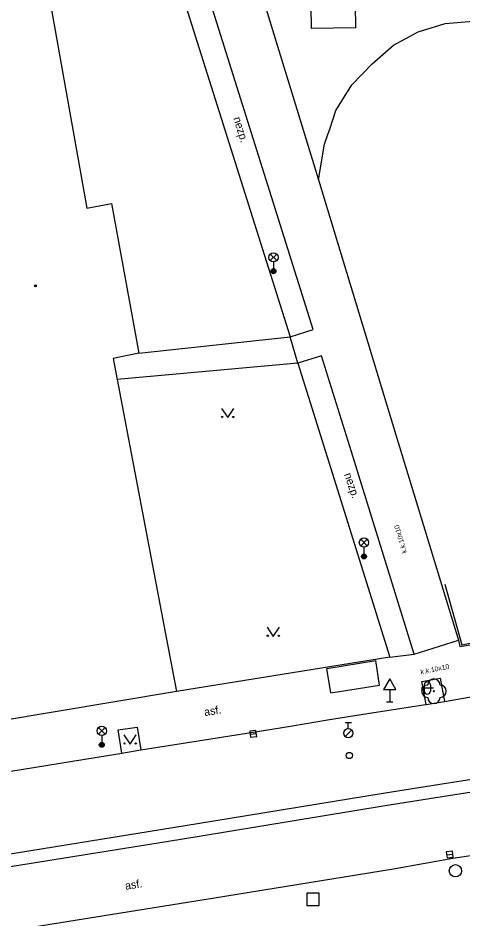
# Model space of a CAD drawing. Extents: x -600309 to -598967, y -1161267 to -1160292.
# Drawn here: x -599181.8 to -599145.7, y -1161124.2 to -1161051.1 of the extents above; entities that cross this region are included whole.
import ezdxf

# ---------------------------------------------------------------- set-up
doc = ezdxf.new("R2010")
doc.units = 0
for name, color, linetype in [('Level 10', 7, 'Continuous'), ('Level 11', 7, 'Continuous'), ('Level 22', 7, 'Continuous'), ('Level 26', 7, 'Continuous'), ('Level 27', 7, 'Continuous'), ('Level 28', 7, 'Continuous'), ('Level 33', 7, 'Continuous'), ('Level 34', 7, 'Continuous'), ('Level 36', 7, 'Continuous'), ('Level 39', 7, 'Continuous'), ('Level 40', 7, 'Continuous'), ('Level 5', 7, 'Continuous'), ('Level 7', 7, 'Continuous'), ('Level 8', 7, 'Continuous'), ('Level 9', 7, 'Continuous')]:
    doc.layers.add(name, color=color, linetype=linetype)

msp = doc.modelspace()

# ---------------------------------------------------------------- linework, layer by layer
at = {"layer": 'Level 10'}
for points in [[(-599147.18, -1161106.56), (-599139.8, -1161105.24)], [(-599171.84, -1161110.48), (-599169.08, -1161110.05), (-599162.7199, -1161109.04), (-599159.53, -1161108.51), (-599156.69, -1161108.03), (-599153.45, -1161107.51), (-599148.74, -1161106.8), (-599148.69, -1161106.79)], [(-599148.69, -1161106.79), (-599147.18, -1161106.56)], [(-599183.6, -1161112.4), (-599173.38, -1161110.75)], [(-599173.38, -1161110.75), (-599171.84, -1161110.48)], [(-599127.19, -1161111.34), (-599131.17, -1161116.8), (-599140.87, -1161118.45), (-599146.51, -1161119.29)], [(-599146.51, -1161119.29), (-599151.34, -1161120.15), (-599165.86, -1161122.5), (-599196.79, -1161127.45), (-599208.59, -1161129.36), (-599217.76, -1161130.81), (-599223.78, -1161126.79)]]:
    msp.add_lwpolyline(points, dxfattribs=at)
at = {"layer": 'Level 11'}
for points in [[(-599159.71, -1161076.94), (-599157.84, -1161076.35), (-599166.53, -1161048.68), (-599167.6599, -1161046.54), (-599175.05, -1161038.42)], [(-599162.5, -1161047.6), (-599157.42, -1161064.19)], [(-599158.03, -1161048.27), (-599154.48, -1161048.1599), (-599154.42, -1161051.87), (-599157.99, -1161051.9099), (-599158.03, -1161048.27)], [(-599157.42, -1161064.19), (-599156.92, -1161061.31), (-599156.67, -1161060.52), (-599156.4699, -1161060), (-599156, -1161058.58), (-599154.7199, -1161056.5), (-599153.06, -1161054.78), (-599151.34, -1161053.28), (-599149.33, -1161052.18), (-599147.14, -1161051.52), (-599144.86, -1161051.33)], [(-599157.42, -1161064.19), (-599151.14, -1161084.9), (-599146.04, -1161101.56)], [(-599172.02, -1161078.26), (-599159.71, -1161076.94)], [(-599149.6599, -1161102.7), (-599154.75, -1161086.28), (-599157.17, -1161078.49), (-599159.09, -1161079.08)], [(-599159.09, -1161079.08), (-599173.76, -1161080.42)], [(-599149.6599, -1161102.7), (-599146.04, -1161101.56)], [(-599146.04, -1161101.56), (-599145.94, -1161102.07), (-599143.03, -1161101.63)], [(-599151.62, -1161102.94), (-599149.6599, -1161102.7)], [(-599156.73, -1161103.87), (-599152.77, -1161103.21)], [(-599152.46, -1161105.22), (-599152.77, -1161103.21)], [(-599156.42, -1161105.84), (-599156.73, -1161103.87)], [(-599148.69, -1161106.79), (-599149.03, -1161104.9099), (-599147.54, -1161104.64), (-599147.18, -1161106.56)], [(-599156.42, -1161105.84), (-599152.46, -1161105.22)], [(-599119.42, -1161109.21), (-599119.94, -1161107.92), (-599131.98, -1161110.59), (-599141.68, -1161112.37), (-599147.5578, -1161113.2881), (-599152.18, -1161114.01), (-599167.25, -1161116.49), (-599181.79, -1161118.82), (-599204.9699, -1161122.5), (-599218.82, -1161124.6599), (-599221.59, -1161124.8), (-599225.08, -1161124.96), (-599236.06, -1161126.61)], [(-599173.38, -1161110.75), (-599173.68, -1161108.86), (-599172.15, -1161108.62), (-599171.84, -1161110.48)], [(-599236.06, -1161126.61), (-599235.9099, -1161127.6), (-599225.55, -1161125.98), (-599221.58, -1161125.8), (-599218.77, -1161125.6599), (-599204.81, -1161123.48), (-599181.6, -1161119.8), (-599169.59, -1161117.88), (-599167.12, -1161117.49), (-599152.01, -1161114.99), (-599147.39, -1161114.27), (-599141.52, -1161113.35), (-599132.1, -1161111.64), (-599125.56, -1161110.17)]]:
    msp.add_lwpolyline(points, dxfattribs=at)
at = {"layer": 'Level 22'}
msp.add_circle((-599148.05, -1161105.71), 0.05, dxfattribs=at)
for centre, start, end in [((-599148.05, -1161105.21), 0, 180), ((-599148.55, -1161105.71), 90, 270), ((-599147.55, -1161105.71), 270, 90), ((-599148.05, -1161106.21), 180, 0)]:
    msp.add_arc(centre, 0.5, start, end, dxfattribs=at)
at = {"layer": 'Level 26'}
msp.add_lwpolyline([(-599158.37, -1161123.1), (-599157.37, -1161123.1), (-599157.37, -1161122.1), (-599158.37, -1161122.1)], close=True, dxfattribs=at)
at = {"layer": 'Level 27'}
for p, q in [((-599162.9679, -1161109.2016), (-599162.4719, -1161109.1384)), ((-599147.008, -1161119.0016), (-599146.512, -1161118.9384))]:
    msp.add_line(p, q, dxfattribs=at)
for points in [[(-599162.9363, -1161109.4496), (-599162.4403, -1161109.3864), (-599162.5035, -1161108.8904), (-599162.9995, -1161108.9536)], [(-599146.9764, -1161119.2496), (-599146.4804, -1161119.1864), (-599146.5436, -1161118.6904), (-599147.0396, -1161118.7536)]]:
    msp.add_lwpolyline(points, close=True, dxfattribs=at)
msp.add_circle((-599146.3, -1161120.29), 0.5, dxfattribs=at)
at = {"layer": 'Level 28'}
for p, q in [((-599155.25, -1161108.245), (-599154.75, -1161108.245)), ((-599155, -1161108.745), (-599155, -1161108.245)), ((-599155.258, -1161109.392), (-599154.728, -1161108.862))]:
    msp.add_line(p, q, dxfattribs=at)
for centre, radius in [((-599155, -1161109.12), 0.375), ((-599154.9099, -1161110.93), 0.25)]:
    msp.add_circle(centre, radius, dxfattribs=at)
at = {"layer": 'Level 33'}
for p, q in [((-599161.345, -1161070.76), (-599160.815, -1161070.23)), ((-599161.345, -1161070.23), (-599160.815, -1161070.76)), ((-599161.08, -1161070.87), (-599161.08, -1161071.62)), ((-599153.995, -1161093.91), (-599153.465, -1161093.38)), ((-599153.995, -1161093.38), (-599153.465, -1161093.91)), ((-599153.73, -1161094.02), (-599153.73, -1161094.77)), ((-599175.285, -1161109.2), (-599174.755, -1161108.67)), ((-599175.285, -1161108.67), (-599174.755, -1161109.2)), ((-599175.02, -1161109.31), (-599175.02, -1161110.06))]:
    msp.add_line(p, q, dxfattribs=at)
for centre, radius in [((-599161.08, -1161070.495), 0.375), ((-599161.08, -1161071.62), 0.2), ((-599161.08, -1161071.62), 0.1445), ((-599161.08, -1161071.62), 0.0876), ((-599153.73, -1161093.645), 0.375), ((-599153.73, -1161094.77), 0.2), ((-599153.73, -1161094.77), 0.1445), ((-599153.73, -1161094.77), 0.0876), ((-599175.02, -1161108.935), 0.375), ((-599175.02, -1161110.06), 0.2), ((-599175.02, -1161110.06), 0.1445), ((-599175.02, -1161110.06), 0.0876)]:
    msp.add_circle(centre, radius, dxfattribs=at)
at = {"layer": 'Level 34'}
for p, q in [((-599151.64, -1161105.562), (-599151.64, -1161106.58)), ((-599151.89, -1161106.58), (-599151.39, -1161106.58))]:
    msp.add_line(p, q, dxfattribs=at)
msp.add_lwpolyline([(-599152.14, -1161105.562), (-599151.14, -1161105.562), (-599151.64, -1161104.696)], close=True, dxfattribs=at)
at = {"layer": 'Level 36'}
for p, q in [((-599149.086, -1161105.446), (-599148.086, -1161105.446)), ((-599148.836, -1161105.196), (-599148.836, -1161105.696)), ((-599148.336, -1161105.196), (-599148.336, -1161105.696))]:
    msp.add_line(p, q, dxfattribs=at)
for points in [[(-599165.29, -1161082.75), (-599164.79, -1161083.5), (-599164.29, -1161082.75)], [(-599161.59, -1161100.51), (-599161.09, -1161101.26), (-599160.59, -1161100.51)], [(-599173.2199, -1161109.26), (-599172.7199, -1161110.01), (-599172.2199, -1161109.26)]]:
    msp.add_lwpolyline(points, dxfattribs=at)
for centre in [(-599165.2402, -1161083.4498), (-599164.3408, -1161083.4498), (-599161.5402, -1161101.2098), (-599160.6408, -1161101.2098), (-599173.1701, -1161109.9598), (-599172.2707, -1161109.9598)]:
    msp.add_circle(centre, 0.05, dxfattribs=at)
for centre, start, end in [((-599148.5857, -1161105.1963), 0, 180), ((-599148.5857, -1161105.6963), 180, 0)]:
    msp.add_arc(centre, 0.25, start, end, dxfattribs=at)
at = {"layer": 'Level 39'}
for radius in [0.09, 0.0398]:
    msp.add_circle((-599180.4, -1161072.81), radius, dxfattribs=at)
at = {"layer": 'Level 5'}
for points in [[(-599180.76, -1161041.12), (-599176.24, -1161066.5)], [(-599176.24, -1161066.5), (-599174.24, -1161066.13)], [(-599174.24, -1161066.13), (-599172.02, -1161078.26)], [(-599172.02, -1161078.26), (-599174.08, -1161078.71)], [(-599174.08, -1161078.71), (-599173.76, -1161080.42), (-599169.86, -1161100.92), (-599168.95, -1161105.74)], [(-599168.95, -1161105.74), (-599183.67, -1161108.2)]]:
    msp.add_lwpolyline(points, dxfattribs=at)
at = {"layer": 'Level 7'}
for points in [[(-599180.88, -1161040.68), (-599176.84, -1161039.98), (-599168.54, -1161048.98), (-599159.71, -1161076.94)], [(-599159.09, -1161079.08), (-599156.01, -1161088.92), (-599151.62, -1161102.94)], [(-599151.62, -1161102.94), (-599168.95, -1161105.74)]]:
    msp.add_lwpolyline(points, dxfattribs=at)
at = {"layer": 'Level 8'}
msp.add_lwpolyline([(-599159.09, -1161079.08), (-599159.71, -1161076.94)], dxfattribs=at)
at = {"layer": 'Level 9'}
msp.add_lwpolyline([(-599147.15, -1161097.03), (-599145.79, -1161101.95), (-599143.28, -1161101.45)], dxfattribs=at)

# ---------------------------------------------------------------- texts
at = {"layer": 'Level 40'}
for s, height, rotation, p in [('nezp.', 0.65, 287.52, (-599164.35, -1161059.2)), ('nezp.', 0.65, 288.74, (-599155.35, -1161088.11)), ('k.k.10x10', 0.4, 106.189703, (-599150.24, -1161094.45)), ('k.k.10x10', 0.4, 11.472822, (-599149.09, -1161104.35)), ('asf.', 0.65, 9, (-599166.6599, -1161107.73)), ('asf.', 0.65, 9, (-599173.08, -1161121.84))]:
    msp.add_text(s, height=height, rotation=rotation, dxfattribs=at).set_placement(p)

doc.saveas('drawing.dxf')
